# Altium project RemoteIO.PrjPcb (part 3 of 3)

## Sheet RemoteIO_CPU_PWR_RST.SchDoc
size 431 x 279 mm; Date: Not shown in title block; ApprovedBy: Not shown in title block; CheckedBy: Not shown in title block; Author: Not shown in title block; CompanyName: Not shown in title block; Engineer: Not shown in title block; Organization: Not shown in title block; Address1: Not shown in title block; Address2: Not shown in title block; Address3: Not shown in title block; Address4: Not shown in title block; DocumentNumber: 9; Revision: Use project parameter SCH_Rev; SheetNumber: 9; SheetTotal: 14; PageSetup: Record=PageOptions¦CenterHorizontal=True¦CenterVertical=True¦PrintScale=1.00¦XCorrection=1.00¦YCorrection=1.00¦PrintKind=0¦BorderSize=5000000¦LeftOffset=0¦BottomOffset=0¦Orientation=2¦PaperLength=1000¦PaperWidth=1000¦Scale=100¦PaperSource=15¦PrintQuality=600¦MediaType=1¦DitherType=10¦PaperKind=Letter¦PrintScaleMode=1
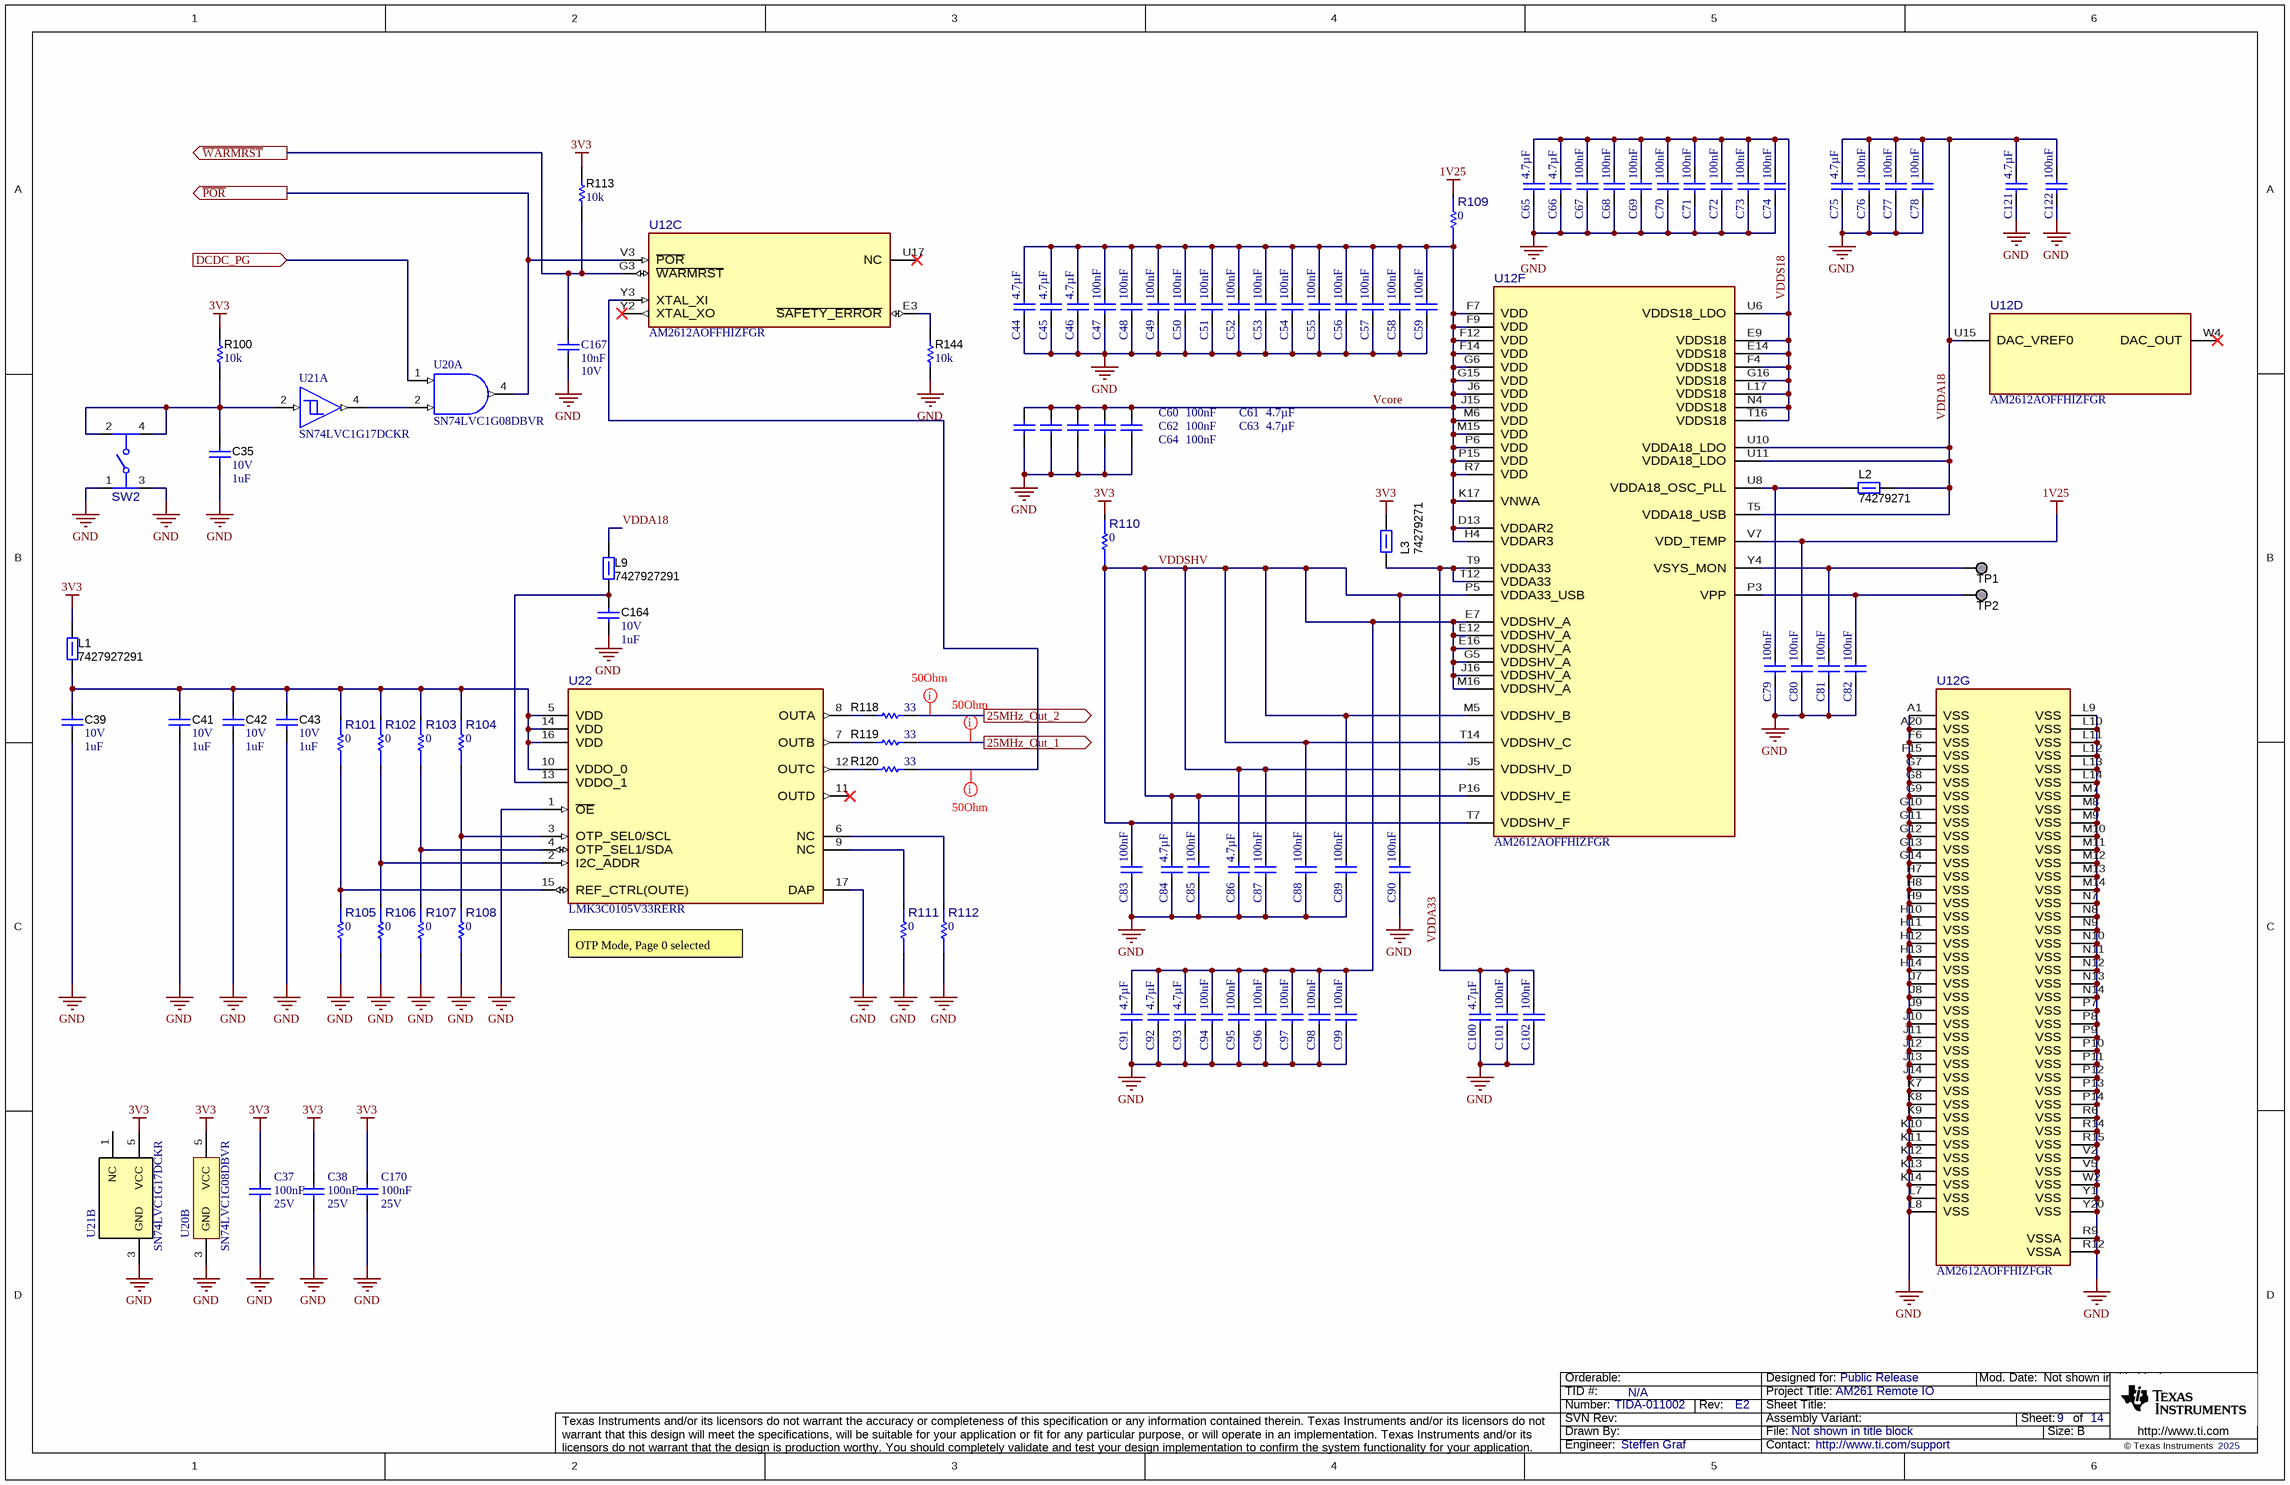
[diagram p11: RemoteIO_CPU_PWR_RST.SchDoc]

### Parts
C35  VDC_V: 10V  ValueDisplayed: 1uF  [0402]  (hidden comment: 885012105012)
C37  Cap_F: 100nF  Rated Voltage (DC): 25V  [WCAP-CSGP_0402_L1W0.5H0.5]  (hidden comment: 885012105018)
C38  Cap_F: 100nF  Rated Voltage (DC): 25V  [WCAP-CSGP_0402_L1W0.5H0.5]  (hidden comment: 885012105018)
C39  VDC_V: 10V  ValueDisplayed: 1uF  [0402]  (hidden comment: 885012105012)
C41  VDC_V: 10V  ValueDisplayed: 1uF  [0402]  (hidden comment: 885012105012)
C42  VDC_V: 10V  ValueDisplayed: 1uF  [0402]  (hidden comment: 885012105012)
C43  VDC_V: 10V  ValueDisplayed: 1uF  [0402]  (hidden comment: 885012105012)
C44  Cap_F: 4.7µF  [WCAP-CSGP_0603_L1.6W0.8H0.8_Reflow]  (hidden comment: 885012106005)
C45  Cap_F: 4.7µF  [WCAP-CSGP_0603_L1.6W0.8H0.8_Reflow]  (hidden comment: 885012106005)
C46  Cap_F: 4.7µF  [WCAP-CSGP_0603_L1.6W0.8H0.8_Reflow]  (hidden comment: 885012106005)
C47  Cap_F: 100nF  [WCAP-CSGP_0201_L0.6W0.3H0.3]  (hidden comment: 885012104009)
C48  Cap_F: 100nF  [WCAP-CSGP_0201_L0.6W0.3H0.3]  (hidden comment: 885012104009)
C49  Cap_F: 100nF  [WCAP-CSGP_0201_L0.6W0.3H0.3]  (hidden comment: 885012104009)
C50  Cap_F: 100nF  [WCAP-CSGP_0201_L0.6W0.3H0.3]  (hidden comment: 885012104009)
C51  Cap_F: 100nF  [WCAP-CSGP_0201_L0.6W0.3H0.3]  (hidden comment: 885012104009)
C52  Cap_F: 100nF  [WCAP-CSGP_0201_L0.6W0.3H0.3]  (hidden comment: 885012104009)
C53  Cap_F: 100nF  [WCAP-CSGP_0201_L0.6W0.3H0.3]  (hidden comment: 885012104009)
C54  Cap_F: 100nF  [WCAP-CSGP_0201_L0.6W0.3H0.3]  (hidden comment: 885012104009)
C55  Cap_F: 100nF  [WCAP-CSGP_0201_L0.6W0.3H0.3]  (hidden comment: 885012104009)
C56  Cap_F: 100nF  [WCAP-CSGP_0201_L0.6W0.3H0.3]  (hidden comment: 885012104009)
C57  Cap_F: 100nF  [WCAP-CSGP_0201_L0.6W0.3H0.3]  (hidden comment: 885012104009)
C58  Cap_F: 100nF  [WCAP-CSGP_0201_L0.6W0.3H0.3]  (hidden comment: 885012104009)
C59  Cap_F: 100nF  [WCAP-CSGP_0201_L0.6W0.3H0.3]  (hidden comment: 885012104009)
C60  Cap_F: 100nF  [WCAP-CSGP_0201_L0.6W0.3H0.3]  (hidden comment: 885012104009)
C61  Cap_F: 4.7µF  [WCAP-CSGP_0603_L1.6W0.8H0.8_Reflow]  (hidden comment: 885012106005)
C62  Cap_F: 100nF  [WCAP-CSGP_0201_L0.6W0.3H0.3]  (hidden comment: 885012104009)
C63  Cap_F: 4.7µF  [WCAP-CSGP_0603_L1.6W0.8H0.8_Reflow]  (hidden comment: 885012106005)
C64  Cap_F: 100nF  [WCAP-CSGP_0201_L0.6W0.3H0.3]  (hidden comment: 885012104009)
C65  Cap_F: 4.7µF  [WCAP-CSGP_0603_L1.6W0.8H0.8_Reflow]  (hidden comment: 885012106005)
C66  Cap_F: 4.7µF  [WCAP-CSGP_0603_L1.6W0.8H0.8_Reflow]  (hidden comment: 885012106005)
C67  Cap_F: 100nF  [WCAP-CSGP_0201_L0.6W0.3H0.3]  (hidden comment: 885012104009)
C68  Cap_F: 100nF  [WCAP-CSGP_0201_L0.6W0.3H0.3]  (hidden comment: 885012104009)
C69  Cap_F: 100nF  [WCAP-CSGP_0201_L0.6W0.3H0.3]  (hidden comment: 885012104009)
C70  Cap_F: 100nF  [WCAP-CSGP_0201_L0.6W0.3H0.3]  (hidden comment: 885012104009)
C71  Cap_F: 100nF  [WCAP-CSGP_0201_L0.6W0.3H0.3]  (hidden comment: 885012104009)
C72  Cap_F: 100nF  [WCAP-CSGP_0201_L0.6W0.3H0.3]  (hidden comment: 885012104009)
C73  Cap_F: 100nF  [WCAP-CSGP_0201_L0.6W0.3H0.3]  (hidden comment: 885012104009)
C74  Cap_F: 100nF  [WCAP-CSGP_0201_L0.6W0.3H0.3]  (hidden comment: 885012104009)
C75  Cap_F: 4.7µF  [WCAP-CSGP_0603_L1.6W0.8H0.8_Reflow]  (hidden comment: 885012106005)
C76  Cap_F: 100nF  [WCAP-CSGP_0201_L0.6W0.3H0.3]  (hidden comment: 885012104009)
C77  Cap_F: 100nF  [WCAP-CSGP_0201_L0.6W0.3H0.3]  (hidden comment: 885012104009)
C78  Cap_F: 100nF  [WCAP-CSGP_0201_L0.6W0.3H0.3]  (hidden comment: 885012104009)
C79  Cap_F: 100nF  [WCAP-CSGP_0201_L0.6W0.3H0.3]  (hidden comment: 885012104009)
C80  Cap_F: 100nF  [WCAP-CSGP_0201_L0.6W0.3H0.3]  (hidden comment: 885012104009)
C81  Cap_F: 100nF  [WCAP-CSGP_0201_L0.6W0.3H0.3]  (hidden comment: 885012104009)
C82  Cap_F: 100nF  [WCAP-CSGP_0201_L0.6W0.3H0.3]  (hidden comment: 885012104009)
C83  Cap_F: 100nF  [WCAP-CSGP_0201_L0.6W0.3H0.3]  (hidden comment: 885012104009)
C84  Cap_F: 4.7µF  [WCAP-CSGP_0603_L1.6W0.8H0.8_Reflow]  (hidden comment: 885012106005)
C85  Cap_F: 100nF  [WCAP-CSGP_0201_L0.6W0.3H0.3]  (hidden comment: 885012104009)
C86  Cap_F: 4.7µF  [WCAP-CSGP_0603_L1.6W0.8H0.8_Reflow]  (hidden comment: 885012106005)
C87  Cap_F: 100nF  [WCAP-CSGP_0201_L0.6W0.3H0.3]  (hidden comment: 885012104009)
C88  Cap_F: 100nF  [WCAP-CSGP_0201_L0.6W0.3H0.3]  (hidden comment: 885012104009)
C89  Cap_F: 100nF  [WCAP-CSGP_0201_L0.6W0.3H0.3]  (hidden comment: 885012104009)
C90  Cap_F: 100nF  [WCAP-CSGP_0201_L0.6W0.3H0.3]  (hidden comment: 885012104009)
C91  Cap_F: 4.7µF  [WCAP-CSGP_0603_L1.6W0.8H0.8_Reflow]  (hidden comment: 885012106005)
C92  Cap_F: 4.7µF  [WCAP-CSGP_0603_L1.6W0.8H0.8_Reflow]  (hidden comment: 885012106005)
C93  Cap_F: 4.7µF  [WCAP-CSGP_0603_L1.6W0.8H0.8_Reflow]  (hidden comment: 885012106005)
C94  Cap_F: 100nF  [WCAP-CSGP_0201_L0.6W0.3H0.3]  (hidden comment: 885012104009)
C95  Cap_F: 100nF  [WCAP-CSGP_0201_L0.6W0.3H0.3]  (hidden comment: 885012104009)
C96  Cap_F: 100nF  [WCAP-CSGP_0201_L0.6W0.3H0.3]  (hidden comment: 885012104009)
C97  Cap_F: 100nF  [WCAP-CSGP_0201_L0.6W0.3H0.3]  (hidden comment: 885012104009)
C98  Cap_F: 100nF  [WCAP-CSGP_0201_L0.6W0.3H0.3]  (hidden comment: 885012104009)
C99  Cap_F: 100nF  [WCAP-CSGP_0201_L0.6W0.3H0.3]  (hidden comment: 885012104009)
C100  Cap_F: 4.7µF  [WCAP-CSGP_0603_L1.6W0.8H0.8_Reflow]  (hidden comment: 885012106005)
C101  Cap_F: 100nF  [WCAP-CSGP_0201_L0.6W0.3H0.3]  (hidden comment: 885012104009)
C102  Cap_F: 100nF  [WCAP-CSGP_0201_L0.6W0.3H0.3]  (hidden comment: 885012104009)
C121  Cap_F: 4.7µF  [WCAP-CSGP_0603_L1.6W0.8H0.8_Reflow]  (hidden comment: 885012106005)
C122  Cap_F: 100nF  [WCAP-CSGP_0201_L0.6W0.3H0.3]  (hidden comment: 885012104009)
C164  VDC_V: 10V  ValueDisplayed: 1uF  [0402]  (hidden comment: 885012105012)
C167  Cap_F: 10nF  Rated Voltage (DC): 10V  [WCAP-CSGP_0402_L1W0.5H0.5]  (hidden comment: 885012205012)
C170  Cap_F: 100nF  Rated Voltage (DC): 25V  [WCAP-CSGP_0402_L1W0.5H0.5]  (hidden comment: 885012105018)
L1  7427927291  [0402]
L2  74279271  [0402]
L3  74279271  [0402]
L9  7427927291  [0402]
R100  ValueDisplayed: 10k  [0402]  (hidden comment: CRCW040210K0JNED)
R101  value 0  [FP-CRCW04020000Z0EDC_0402-MFG]  (hidden comment: CRCW04020000Z0EDC)
R102  value 0  [FP-CRCW04020000Z0EDC_0402-MFG]  (hidden comment: CRCW04020000Z0EDC)
R103  value 0  [FP-CRCW04020000Z0EDC_0402-MFG]  (hidden comment: CRCW04020000Z0EDC)
R104  value 0  [FP-CRCW04020000Z0EDC_0402-MFG]  (hidden comment: CRCW04020000Z0EDC)
R105  value 0  [FP-CRCW04020000Z0EDC_0402-MFG]  (hidden comment: CRCW04020000Z0EDC)
R106  value 0  [FP-CRCW04020000Z0EDC_0402-MFG]  (hidden comment: CRCW04020000Z0EDC)
R107  value 0  [FP-CRCW04020000Z0EDC_0402-MFG]  (hidden comment: CRCW04020000Z0EDC)
R108  value 0  [FP-CRCW04020000Z0EDC_0402-MFG]  (hidden comment: CRCW04020000Z0EDC)
R109  value 0  [FP-CRCW04020000Z0EDC_0402-MFG]  (hidden comment: CRCW04020000Z0EDC)
R110  value 0  [FP-CRCW04020000Z0EDC_0402-MFG]  (hidden comment: CRCW04020000Z0EDC)
R111  value 0  [FP-CRCW04020000Z0EDC_0402-MFG]  (hidden comment: CRCW04020000Z0EDC)
R112  value 0  [FP-CRCW04020000Z0EDC_0402-MFG]  (hidden comment: CRCW04020000Z0EDC)
R113  ValueDisplayed: 10k  [0402]  (hidden comment: CRCW040210K0JNED)
R118  ValueDisplayed: 33  [0402]  (hidden comment: CRCW040233R0JNED)
R119  ValueDisplayed: 33  [0402]  (hidden comment: CRCW040233R0JNED)
R120  ValueDisplayed: 33  [0402]  (hidden comment: CRCW040233R0JNED)
R144  ValueDisplayed: 10k  [0402]  (hidden comment: CRCW040210K0JNED)
SW2  434351045816  [FP-434351045816_SMT_SW_4MM7_4MM5-MFG]  (value not drawn)
TP1  TP_SM_1MM  [TP_SM_1MM]  (value not drawn)  (no BOM)
TP2  TP_SM_1MM  [TP_SM_1MM]  (value not drawn)  (no BOM)
U12  AM2612AOFFHIZFGR  [ZFG0304A-MFG]  (parts C,D,F,G of 7)
U20  SN74LVC1G08DBVR  [DBV0005A_N]  (parts A,B of 2)
U21  SN74LVC1G17DCKR  [DCK0005A_N]  (parts A,B of 2)
U22  LMK3C0105V33RERR  [RER0016A-MFG]

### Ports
25MHz_Out_1 (out), 25MHz_Out_2 (out), DCDC_PG (in), ~{POR} (out), ~{WARMRST} (out)

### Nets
1V25: C80.2 R109.2 U12.V7(VDD_TEMP)
3V3: C37.2 C38.2 C170.2 L1.2 L3.2 R100.2 R110.2 R113.1 U20.5(VCC) U21.5(VCC)
GND: C35.2 C37.1 C38.1 C39.2 C41.2 C42.2 C43.2 C44.1 C45.1 C46.1 C47.1 C48.1 C49.1 C50.1 C51.1 C52.1 C53.1 C54.1 C55.1 C56.1 C57.1 C58.1 C59.1 C60.1 C61.1 C62.1 C63.1 C64.1 C65.1 C66.1 C67.1 C68.1 C69.1 C70.1 C71.1 C72.1 C73.1 C74.1 C75.1 C76.1 C77.1 C78.1 C79.1 C80.1 C81.1 C82.1 C83.1 C84.1 C85.1 C86.1 C87.1 C88.1 C89.1 C90.1 C91.1 C92.1 C93.1 C94.1 C95.1 C96.1 C97.1 C98.1 C99.1 C100.1 C101.1 C102.1 C121.1 C122.1 C164.2 C167.1 C170.1 R105.1 R106.1 R107.1 R108.1 R111.1 R112.1 R144.1 SW2.1 SW2.3 U12.A1(VSS) U12.A20(VSS) U12.F6(VSS) U12.F15(VSS) U12.G7(VSS) U12.G8(VSS) U12.G9(VSS) U12.G10(VSS) U12.G11(VSS) U12.G12(VSS) U12.G13(VSS) U12.G14(VSS) U12.H7(VSS) U12.H8(VSS) U12.H9(VSS) U12.H10(VSS) U12.H11(VSS) U12.H12(VSS) U12.H13(VSS) U12.H14(VSS) U12.J7(VSS) U12.J8(VSS) U12.J9(VSS) U12.J10(VSS) U12.J11(VSS) U12.J12(VSS) U12.J13(VSS) U12.J14(VSS) U12.K7(VSS) U12.K8(VSS) U12.K9(VSS) U12.K10(VSS) U12.K11(VSS) U12.K12(VSS) U12.K13(VSS) U12.K14(VSS) U12.L7(VSS) U12.L8(VSS) U12.L9(VSS) U12.L10(VSS) U12.L11(VSS) U12.L12(VSS) U12.L13(VSS) U12.L14(VSS) U12.M7(VSS) U12.M8(VSS) U12.M9(VSS) U12.M10(VSS) U12.M11(VSS) U12.M12(VSS) U12.M13(VSS) U12.M14(VSS) U12.N7(VSS) U12.N8(VSS) U12.N9(VSS) U12.N10(VSS) U12.N11(VSS) U12.N12(VSS) U12.N13(VSS) U12.N14(VSS) U12.P7(VSS) U12.P8(VSS) U12.P9(VSS) U12.P10(VSS) U12.P11(VSS) U12.P12(VSS) U12.P13(VSS) U12.P14(VSS) U12.R6(VSS) U12.R9(VSSA) U12.R12(VSSA) U12.R14(VSS) U12.R15(VSS) U12.V2(VSS) U12.V5(VSS) U12.W2(VSS) U12.Y1(VSS) U12.Y20(VSS) U20.3(GND) U21.3(GND) U22.1(~{OE}) U22.17(DAP)
25MHz: R119.2 ; port 25MHz_Out_1
25MHz: R118.2 ; port 25MHz_Out_2  [a separate net that carries the same name]
~{POR}: U12.V3(~{POR}) U20.4(Y) ; port ~{POR}
~{WARMRST}: C167.2 R113.2 U12.G3(~{WARMRST}) ; port ~{WARMRST}
DCDC_PG: U20.1(A) ; port DCDC_PG
Vcore: C44.2 C45.2 C46.2 C47.2 C48.2 C49.2 C50.2 C51.2 C52.2 C53.2 C54.2 C55.2 C56.2 C57.2 C58.2 C59.2 C60.2 C61.2 C62.2 C63.2 C64.2 R109.1 U12.D13(VDDAR2) U12.F7(VDD) U12.F9(VDD) U12.F12(VDD) U12.F14(VDD) U12.G6(VDD) U12.G15(VDD) U12.H4(VDDAR3) U12.J6(VDD) U12.J15(VDD) U12.K17(VNWA) U12.M6(VDD) U12.M15(VDD) U12.P6(VDD) U12.P15(VDD) U12.R7(VDD)
VDDA18: C75.2 C76.2 C77.2 C78.2 C121.2 C122.2 L2.2 L9.2 U12.T5(VDDA18_USB) U12.U10(VDDA18_LDO) U12.U11(VDDA18_LDO) U12.U15(DAC_VREF0)
VDDA33: C100.2 C101.2 C102.2 L3.1 U12.T9(VDDA33) U12.T12(VDDA33)
VDDS18: C65.2 C66.2 C67.2 C68.2 C69.2 C70.2 C71.2 C72.2 C73.2 C74.2 U12.E9(VDDS18) U12.E14(VDDS18) U12.F4(VDDS18) U12.G16(VDDS18) U12.L17(VDDS18) U12.N4(VDDS18) U12.T16(VDDS18) U12.U6(VDDS18_LDO)
VDDSHV: C83.2 C84.2 C85.2 C86.2 C87.2 C88.2 C89.2 C90.2 C91.2 C92.2 C93.2 C94.2 C95.2 C96.2 C97.2 C98.2 C99.2 R110.1 U12.E7(VDDSHV_A) U12.E12(VDDSHV_A) U12.E16(VDDSHV_A) U12.G5(VDDSHV_A) U12.J5(VDDSHV_D) U12.J16(VDDSHV_A) U12.M5(VDDSHV_B) U12.M16(VDDSHV_A) U12.P5(VDDA33_USB) U12.P16(VDDSHV_E) U12.T7(VDDSHV_F) U12.T14(VDDSHV_C)
NetC35_1: C35.1 R100.1 SW2.2 SW2.4 U21.2(A)
NetC39_1: C39.1 C41.1 C42.1 C43.1 L1.1 R101.2 R102.2 R103.2 R104.2 U22.5(VDD) U22.10(VDDO_0) U22.14(VDD) U22.16(VDD)
NetC79_2: C79.2 L2.1 U12.U8(VDDA18_OSC_PLL)
NetC81_2: C81.2 TP1.1 U12.Y4(VSYS_MON)
NetC82_2: C82.2 TP2.1 U12.P3(VPP)
NetC164_1: C164.1 L9.1 U22.13(VDDO_1)
NetR101_1: R101.1 R105.2 U22.15(REF_CTRL(OUTE))
NetR102_1: R102.1 R106.2 U22.2(I2C_ADDR)
NetR103_1: R103.1 R107.2 U22.4(OTP_SEL1/SDA)
NetR104_1: R104.1 R108.2 U22.3(OTP_SEL0/SCL)
NetR111_2: R111.2 U22.9(NC)
NetR112_2: R112.2 U22.6(NC)
NetR118_1: R118.1 U22.8(OUTA)
NetR119_1: R119.1 U22.7(OUTB)
NetR120_1: R120.1 U22.12(OUTC)
NetR120_2: R120.2 U12.Y3(XTAL_XI)
NetR144_2: R144.2 U12.E3(~{SAFETY_ERROR})
NetU20_2: U20.2(B) U21.4(Y)

Not connected (* = marked no-connect by the designer): U12 U17(NC)* W4(DAC_OUT)* Y2(XTAL_XO)*; U21 1(NC); U22 11(OUTD)*

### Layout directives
net class S50: 25MHz, NetR120_2

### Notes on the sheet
- (near U22) OTP Mode, Page 0 selected

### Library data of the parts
C35 C39 C41-C43 C164 = CMP-0064924-2: CAP, CERM, 1 uF, 10 V,+/- 20%, X5R, 0402; Manufacturer: Wurth Elektronik; TaMin_C: -55°C; Polarized: N; SizeAreaWB_mm2: 3; Value1: Unknown; U/M: EA; Value: 1uF; TaMax_C: 85°C; SizeZ_mm: 0.6; SizeX_mm: 1; SizeY_mm: 0.5; Cap_F: 1µF; AEC Category: Q200
C37 C38 C170 = CMP-0119143-1: WCAP-CSGP Multilayer Ceramic Chip Capacitor, General Purpose, size 0402, X5R, 100nF, 25VDC; Manufacturer: Wurth Elektronik; PartNumber: '885012105018; Capacitance Tolerance: +/-20%; Case/Size Code: 0402; Dissipation Factor: 10%; Insulation Resistance: 5GOhm; Technical Reference: X5R0402104M025DFCT10000
C44-C46 C61 C63 C65 C66 C75 C84 C86 C91-C93 C100 C121 = CMP-0119149-1: WCAP-CSGP Multilayer Ceramic Chip Capacitor, General Purpose, size 0603, X5R, 4.7µF, 6.3VDC; Manufacturer: Wurth Elektronik; Capacitance Tolerance: +/-20%; Case/Size Code: 0603; Dissipation Factor: 10%; Insulation Resistance: 0.02GOhm; Rated Voltage (DC): 6.3V; Technical Reference: X5R0603475M6R3DFCT10000
C47-C60 C62 C64 C67-C74 C76-C83 C85 C87-C90 C94-C99 C101 C102 C122 = CMP-0119120-1: WCAP-CSGP Multilayer Ceramic Chip Capacitor, General Purpose, size 0201, X5R Class II, 100nF, 6.3VDC; Manufacturer: Wurth Elektronik; Capacitance Tolerance: +/-10%; Case/Size Code: 0201; Dissipation Factor: 10%; Insulation Resistance: 0.5GOhm; Rated Voltage (DC): 6.3V; Technical Reference: X5R0201104K6R3DFCT10000
C167 = CMP-0119242-1: WCAP-CSGP Multilayer Ceramic Chip Capacitor, General Purpose, size 0402, X7R, 10nF, 10VDC; Manufacturer: Wurth Elektronik; Capacitance Tolerance: +/-10%; Case/Size Code: 0402; Dissipation Factor: 5%; Insulation Resistance: 10GOhm; Technical Reference: X7R0402103K010DFCT10000
L1 L9 = CMP-0003233-1: Ferrite Bead, 600 ohm @ 100 MHz, 0.3 A, 0402; Manufacturer: Wurth Elektronik; Ztyp@1GHz_Ohm: 385.838; ZTyp@100MHz_Ohm: 600; SizeAreaWB_mm2: 3; DCR_ohm: 0.6; Value1: 0.6 ohm; Value: 600 ohm; Imax_A: 300mA; SizeX_mm: 1; SizeY_mm: 0.5; Value2: 0.3A
L2 L3 = CMP-0003214-1: Ferrite Bead, 120 ohm @ 100 MHz, 0.5 A, 0402; Manufacturer: Wurth Elektronik; Ztyp@1GHz_Ohm: 175.42; ZTyp@100MHz_Ohm: 120; SizeAreaWB_mm2: 3; DCR_ohm: 0.2; Value1: 0.2 ohm; Value: 120 ohm; Imax_A: 500mA; SizeZ_mm: 0.6; SizeX_mm: 1; SizeY_mm: 0.5; Value2: 0.5A
R100 R113 R144 = CMP-0026825-5: RES, 10 k, 5%, 0.063 W, AEC-Q200 Grade 0, 0402; Manufacturer: Vishay-Dale; Power_W: 63mW; TempCo: 200 ppm/C; Value_Code: 10k0; Value: 10k; EIA_Code: E24; SizeX_mm: 1; SizeY_mm: 0.5; SizeZ_mm: 0.6; Value2: 0.063W; AEC Qualified: Y; VDC_V: 50V; AEC Category: Q200; AEC Grade: 0
R101-R112 = CMP-0093210-1: Jumper 0.063W, 1/16W Chip Resistor 0402 (1005 Metric) - Thick Film; Manufacturer: Vishay; AEC Qualified: No; VDC_V: 50V; Power_W: 63mW; SizeZ_mm: 0.35mm
R118-R120 = CMP-0026908-3: RES, 33, 5%, 0.063 W, AEC-Q200 Grade 0, 0402; Manufacturer: Vishay-Dale; Power_W: 63mW; TempCo: 200 ppm/C; Value_Code: 33R0; Value: 33; EIA_Code: E24; SizeX_mm: 1; SizeY_mm: 0.5; SizeZ_mm: 0.6; Value2: 0.063W; AEC Qualified: Y; VDC_V: 50V; AEC Category: Q200; AEC Grade: 0
SW2 = CMP-0093456-1: Tactile Switch SPST-NO Side Actuated Surface Mount, Right Angle; Manufacturer: Wurth Electronics; Operating Force: 160gf; SizeZ_mm: 1.75mm; AEC Qualified: No; Electromechanical Life: 200000Cycles; VDC_V: 12V; Contact Current Rating: 50mA; Coil Resistance_ohm: 100mΩ
TP1 TP2 = CMP-0003825-1: 1mm Test Point, SMT; Manufacturer: Any
U12 = CMP-0126016-1: ARM® Cortex®-R5F Sitara™ Microcontroller IC 32-Bit Dual-Core 500MHz 512KB (512K x 8) Tightly Coupled Memory (TCM) 304-NFBGA (13.25x13.25); Manufacturer: Texas Instruments; SizeZ_mm: 1.3mm; AEC Qualified: No; Core Architecture: ARM Cortex-R5F; Data Bus Width: 32bits; Interface: I2C,SPI,UART,CAN,USB,LIN,Ethernet; Max Supply Voltage: 3.465V; Min Supply Voltage: 1.14V; Number Of A/D Converters: 3; Number Of Adc Channels: 7; Number Of Cores: 2; Number Of Ethernet Channels: 1; Number Of I/Os: 141; Number Of Pwm Channels: 10; Number Of Spi Channels: 4; Number Of Uart Channels: 6; Ram Size: 1.5MBytes; Standoff Height: 0.23mm; TJmax_C: +125°C
U20 = CMP-0051588-2: Single 2-Input Positive-AND Gate, DBV0005A, LARGE T&R; Manufacturer: Texas Instruments; Logic: True; ICC @ Nom Voltage(Max)(mA): 0.01; VCC(Min)(V): 1.65; Bits(#): 1; Rating: Catalog; Schmitt Trigger: No; Voltage(Nom)(V): 1.8,2.5,3.3,5; Output Drive (IOL/IOH)(Max)(mA): 32/-32; Gate Type: AND; tpd @ Nom Voltage(Max)(ns): 4.5,6,4,5; VCC(Max)(V): 5.5; Output Type: CMOS; F @ Nom Voltage(Max)(Mhz): 150; Input Type: CMOS/TTL; Technology Family: LVC; AEC Category: Q200; AEC Qualified: N; CompType: IC
U21 = CMP-0051704-3: Single Schmitt-Trigger Buffer, DCK0005A, LARGE T&R; Manufacturer: Texas Instruments; tpd @ Nom Voltage(Max)(ns): 11,6.5,5.5,5; Bits(#): 1; VCC(Min)(V): 1.65; F @ Nom Voltage(Max)(Mhz): 150; VCC(Max)(V): 5.5; Input Type: CMOS/TTL; Sub-Family: Non-Inverting Buffer/Driver; Output Type: CMOS; Output Drive (IOL/IOH)(Max)(mA): 32/-32; 3-State Output: No; Logic: True; ICC @ Nom Voltage(Max)(mA): 0.01; Voltage(Nom)(V): 1.8,2.5,3.3,5; Rating: Catalog; Schmitt Trigger: Yes; Technology Family: LVC; AEC Category: Q200; AEC Qualified: N; CompType: IC; SizeAreaWB_mm2: 9.3; SizeArea_mm2: 4.2; SizeX_mm: 2.1; SizeY_mm: 2.0; SizeZ_mm: 1.1
U22 = CMP-0126121-1: 5 output reference-less clock generator with bulk acoustic wave (BAW) 16-TQFN -40 to 85; Manufacturer: Texas Instruments; SizeZ_mm: 1.2mm; AEC Qualified: No; Interface: I2C; Max Frequency: 200MHz; Max Supply Voltage: 3.465V; Min Supply Voltage: 1.71V; Number Of Outputs: 5; Standoff Height: 0mm; TaMax_C: +85°C; TaMin_C: -40°C; TJmax_C: +105°C

## Sheet RemoteIO_CPU_MISC.SchDoc
size 431 x 279 mm; Date: Not shown in title block; ApprovedBy: Not shown in title block; CheckedBy: Not shown in title block; Author: Not shown in title block; CompanyName: Not shown in title block; Engineer: Not shown in title block; Organization: Not shown in title block; Address1: Not shown in title block; Address2: Not shown in title block; Address3: Not shown in title block; Address4: Not shown in title block; DocumentNumber: 10; Revision: Use project parameter SCH_Rev; SheetNumber: 10; SheetTotal: 14; PageSetup: Record=PageOptions¦CenterHorizontal=True¦CenterVertical=True¦PrintScale=1.00¦XCorrection=1.00¦YCorrection=1.00¦PrintKind=0¦BorderSize=5000000¦LeftOffset=0¦BottomOffset=0¦Orientation=2¦PaperLength=1000¦PaperWidth=1000¦Scale=100¦PaperSource=15¦PrintQuality=600¦MediaType=1¦DitherType=10¦PaperKind=Letter¦PrintScaleMode=1
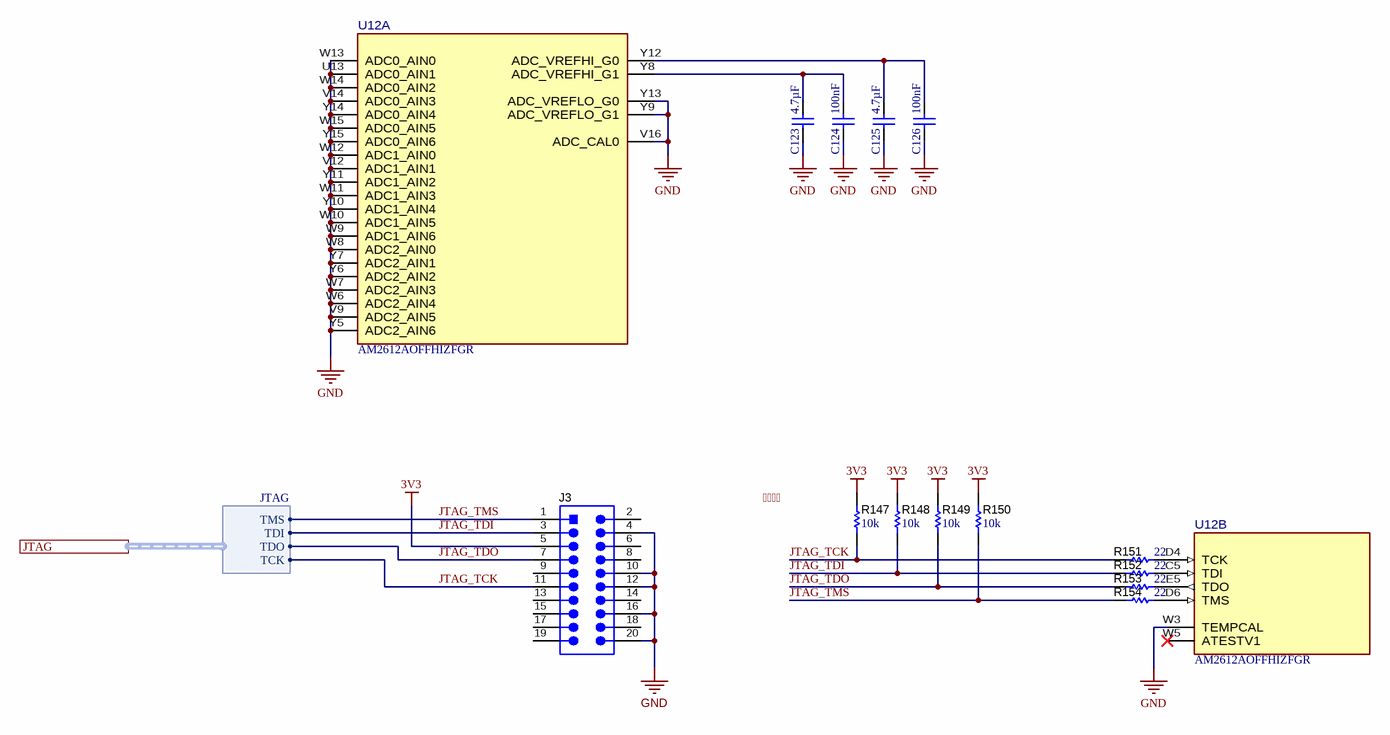
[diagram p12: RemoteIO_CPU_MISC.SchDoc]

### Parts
C123  Cap_F: 4.7µF  [WCAP-CSGP_0603_L1.6W0.8H0.8_Reflow]  (hidden comment: 885012106005)
C124  Cap_F: 100nF  [WCAP-CSGP_0201_L0.6W0.3H0.3]  (hidden comment: 885012104009)
C125  Cap_F: 4.7µF  [WCAP-CSGP_0603_L1.6W0.8H0.8_Reflow]  (hidden comment: 885012106005)
C126  Cap_F: 100nF  [WCAP-CSGP_0201_L0.6W0.3H0.3]  (hidden comment: 885012104009)
J3  FTR-110-51-S-D-06  [Samtec_FTR-110-51-x-D-06]  (value not drawn)
R147  ValueDisplayed: 10k  [0402]  (hidden comment: CRCW040210K0JNED)
R148  ValueDisplayed: 10k  [0402]  (hidden comment: CRCW040210K0JNED)
R149  ValueDisplayed: 10k  [0402]  (hidden comment: CRCW040210K0JNED)
R150  ValueDisplayed: 10k  [0402]  (hidden comment: CRCW040210K0JNED)
R151  ValueDisplayed: 22  [0402]  (hidden comment: CRCW040222R0JNED)
R152  ValueDisplayed: 22  [0402]  (hidden comment: CRCW040222R0JNED)
R153  ValueDisplayed: 22  [0402]  (hidden comment: CRCW040222R0JNED)
R154  ValueDisplayed: 22  [0402]  (hidden comment: CRCW040222R0JNED)
U12  AM2612AOFFHIZFGR  [ZFG0304A-MFG]  (parts A,B of 7)

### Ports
JTAG (harness JTAG)

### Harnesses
JTAG: TMS, TDI, TDO, TCK

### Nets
3V3: J3.5 R147.2 R148.2 R149.2 R150.2
GND: C123.1 C124.1 C125.1 C126.1 J3.4 J3.10 J3.12 J3.16 J3.20 U12.U13(ADC0_AIN1) U12.V9(ADC2_AIN5) U12.V12(ADC1_AIN1) U12.V14(ADC0_AIN3) U12.V16(ADC_CAL0) U12.W3(TEMPCAL) U12.W6(ADC2_AIN4) U12.W7(ADC2_AIN3) U12.W8(ADC2_AIN0) U12.W9(ADC1_AIN6) U12.W10(ADC1_AIN5) U12.W11(ADC1_AIN3) U12.W12(ADC1_AIN0) U12.W13(ADC0_AIN0) U12.W14(ADC0_AIN2) U12.W15(ADC0_AIN5) U12.Y5(ADC2_AIN6) U12.Y6(ADC2_AIN2) U12.Y7(ADC2_AIN1) U12.Y9(ADC_VREFLO_G1) U12.Y10(ADC1_AIN4) U12.Y11(ADC1_AIN2) U12.Y13(ADC_VREFLO_G0) U12.Y14(ADC0_AIN4) U12.Y15(ADC0_AIN6)
JTAG_TCK: J3.11 R147.1 R151.1 ; port JTAG.TCK
JTAG_TDI: J3.3 R148.1 R152.1 ; port JTAG.TDI
JTAG_TDO: J3.7 R149.1 R153.1 ; port JTAG.TDO
JTAG_TMS: J3.1 R150.1 R154.1 ; port JTAG.TMS
NetC123_2: C123.2 C124.2 U12.Y8(ADC_VREFHI_G1)
NetC125_2: C125.2 C126.2 U12.Y12(ADC_VREFHI_G0)
NetR151_2: R151.2 U12.D4(TCK)
NetR152_2: R152.2 U12.C5(TDI)
NetR153_2: R153.2 U12.E5(TDO)
NetR154_2: R154.2 U12.D6(TMS)

Not connected (* = marked no-connect by the designer): J3 2 6 8 9 13 14 15 17 18 19; U12 W5(ATESTV1)*

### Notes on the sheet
- Labels drawn without touching a wire or pin: 

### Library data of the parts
C123 C125 = CMP-0119149-1: as C44 on sheet RemoteIO_CPU_PWR_RST
C124 C126 = CMP-0119120-1: as C47 on sheet RemoteIO_CPU_PWR_RST
J3 = CMP-0075640-2: Header, 1.27mm, 10x2, Tin, SMT; Manufacturer: Samtec; Pitch_mm: 1.27; Gender: Male; Cert_UL: Y; Green_REACh: Passed; Current_A: 3.1A; Shrouded: N; RowSpacing_mm: 2.54; Green_Lifecycle: Active; Row_Count: 2
R147-R150 = CMP-0026825-5: as R100 on sheet RemoteIO_CPU_PWR_RST
R151-R154 = CMP-0026880-3: RES, 22, 5%, 0.063 W, AEC-Q200 Grade 0, 0402; Manufacturer: Vishay-Dale; Power_W: 63mW; TempCo: 200 ppm/C; Value_Code: 22R0; Value: 22; EIA_Code: E24; SizeX_mm: 1; SizeY_mm: 0.5; SizeZ_mm: 0.6; Value2: 0.063W; AEC Qualified: Y; VDC_V: 50V; AEC Category: Q200; AEC Grade: 0
U12 = CMP-0126016-1: as U12 on sheet RemoteIO_CPU_PWR_RST

## Sheet RemoteIO_XDS110.SchDoc
size 431 x 279 mm; Date: Not shown in title block; ApprovedBy: Not shown in title block; CheckedBy: Not shown in title block; Author: Not shown in title block; CompanyName: Not shown in title block; Engineer: Not shown in title block; Organization: Not shown in title block; Address1: Not shown in title block; Address2: Not shown in title block; Address3: Not shown in title block; Address4: Not shown in title block; DocumentNumber: 13; Revision: Use project parameter SCH_Rev; SheetNumber: 13; SheetTotal: 14; PageSetup: Record=PageOptions¦CenterHorizontal=True¦CenterVertical=True¦PrintScale=1.00¦XCorrection=1.00¦YCorrection=1.00¦PrintKind=0¦BorderSize=5000000¦LeftOffset=0¦BottomOffset=0¦Orientation=2¦PaperLength=1000¦PaperWidth=1000¦Scale=100¦PaperSource=15¦PrintQuality=600¦MediaType=1¦DitherType=10¦PaperKind=Letter¦PrintScaleMode=1
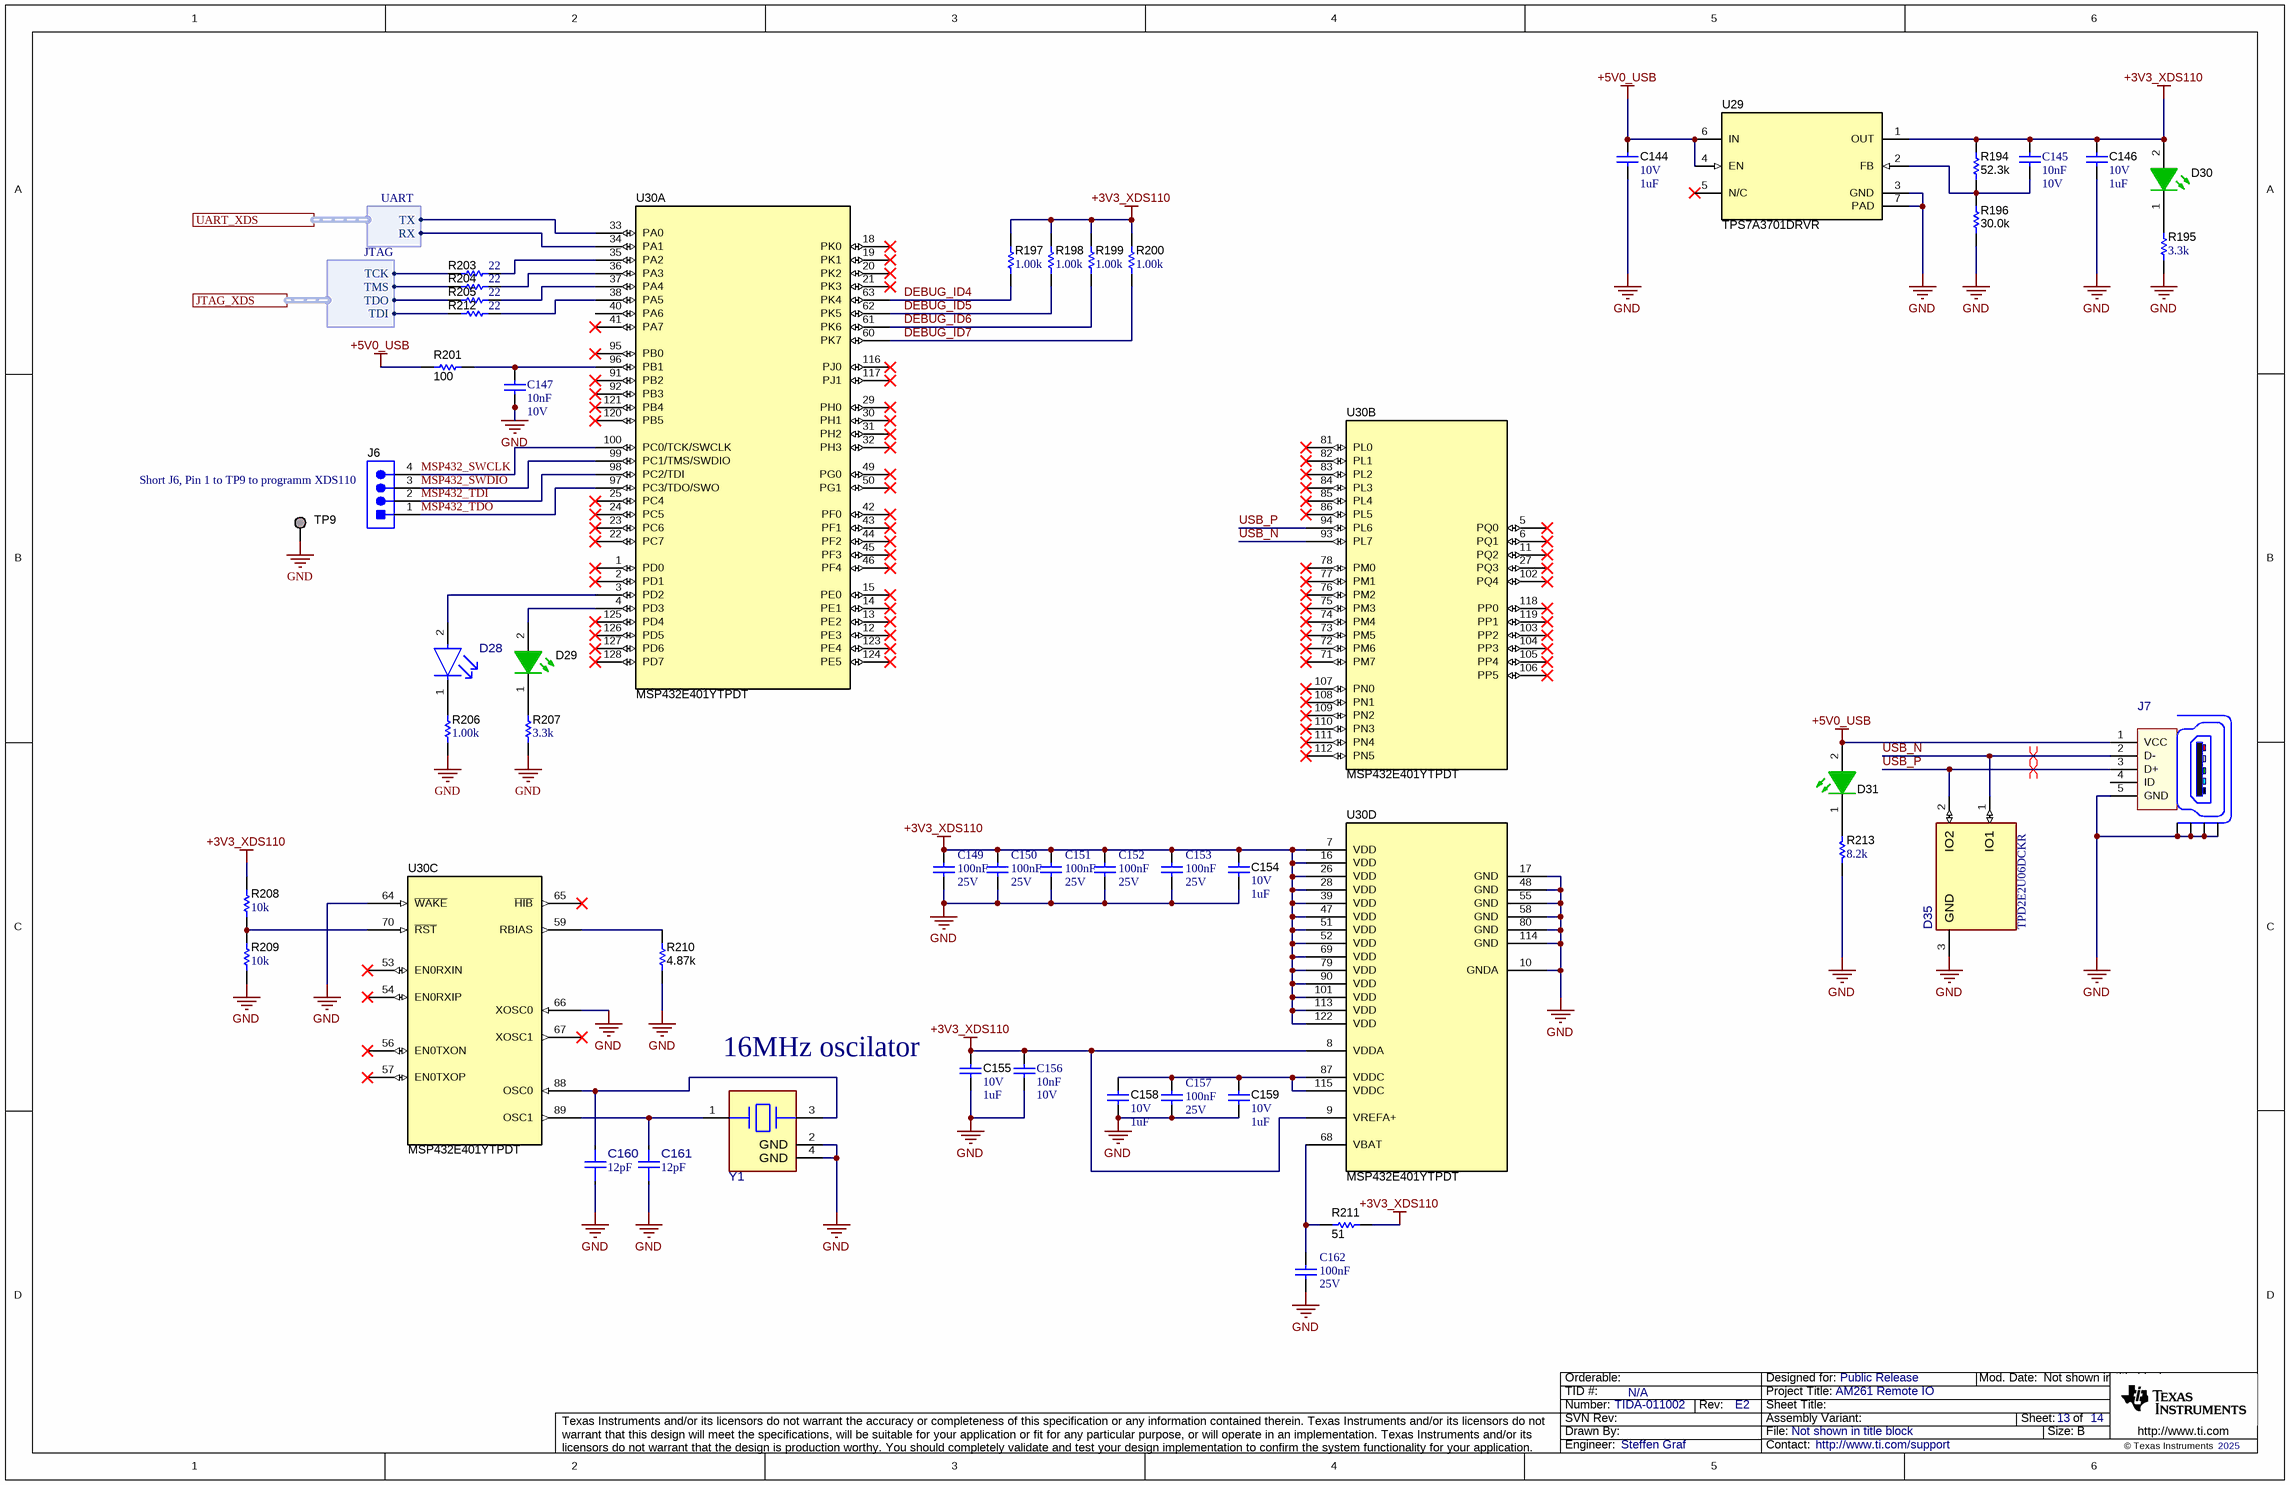
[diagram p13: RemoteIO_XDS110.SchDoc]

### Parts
C144  VDC_V: 10V  ValueDisplayed: 1uF  [0402]  (hidden comment: 885012105012)
C145  Cap_F: 10nF  Rated Voltage (DC): 10V  [WCAP-CSGP_0402_L1W0.5H0.5]  (hidden comment: 885012205012)
C146  VDC_V: 10V  ValueDisplayed: 1uF  [0402]  (hidden comment: 885012105012)
C147  Cap_F: 10nF  Rated Voltage (DC): 10V  [WCAP-CSGP_0402_L1W0.5H0.5]  (hidden comment: 885012205012)
C149  Cap_F: 100nF  Rated Voltage (DC): 25V  [WCAP-CSGP_0402_L1W0.5H0.5]  (hidden comment: 885012105018)
C150  Cap_F: 100nF  Rated Voltage (DC): 25V  [WCAP-CSGP_0402_L1W0.5H0.5]  (hidden comment: 885012105018)
C151  Cap_F: 100nF  Rated Voltage (DC): 25V  [WCAP-CSGP_0402_L1W0.5H0.5]  (hidden comment: 885012105018)
C152  Cap_F: 100nF  Rated Voltage (DC): 25V  [WCAP-CSGP_0402_L1W0.5H0.5]  (hidden comment: 885012105018)
C153  Cap_F: 100nF  Rated Voltage (DC): 25V  [WCAP-CSGP_0402_L1W0.5H0.5]  (hidden comment: 885012105018)
C154  VDC_V: 10V  ValueDisplayed: 1uF  [0402]  (hidden comment: 885012105012)
C155  VDC_V: 10V  ValueDisplayed: 1uF  [0402]  (hidden comment: 885012105012)
C156  Cap_F: 10nF  Rated Voltage (DC): 10V  [WCAP-CSGP_0402_L1W0.5H0.5]  (hidden comment: 885012205012)
C157  Cap_F: 100nF  Rated Voltage (DC): 25V  [WCAP-CSGP_0402_L1W0.5H0.5]  (hidden comment: 885012105018)
C158  VDC_V: 10V  ValueDisplayed: 1uF  [0402]  (hidden comment: 885012105012)
C159  VDC_V: 10V  ValueDisplayed: 1uF  [0402]  (hidden comment: 885012105012)
C160  ValueDisplayed: 12pF  [FP-885392005127_0402-MFG]  (hidden comment: 885392005127)
C161  ValueDisplayed: 12pF  [FP-885392005127_0402-MFG]  (hidden comment: 885392005127)
C162  Cap_F: 100nF  Rated Voltage (DC): 25V  [WCAP-CSGP_0402_L1W0.5H0.5]  (hidden comment: 885012105018)
D28  150040RS73240  [FP-150040RS73220_0402-MFG]  (value not drawn)
D29  150040GS73240  [WL-SMCC_0402_Green]  (value not drawn)
D30  150040GS73240  [WL-SMCC_0402_Green]  (value not drawn)
D31  150040GS73240  [WL-SMCC_0402_Green]  (value not drawn)
D35  TPD2E2U06DCKR  [DCK0003A-MFG]
J6  SPI Debug Header  [WURTH_61300411121]  (value not drawn)
J7  629105150521  [FP-629105150521_CONN_USB_8MM0_6MM6-MFG]  (value not drawn)
R194  ValueDisplayed: 52.3k  [0402]  (hidden comment: CRCW040252K3FKED)
R195  ValueDisplayed: 3.3k  [0402]  (hidden comment: CRCW04023K30JNED)
R196  ValueDisplayed: 30.0k  [0402]  (hidden comment: CRCW040230K0FKED)
R197  ValueDisplayed: 1.00k  [0402]  (hidden comment: CRCW04021K00FKED)
R198  ValueDisplayed: 1.00k  [0402]  (hidden comment: CRCW04021K00FKED)
R199  ValueDisplayed: 1.00k  [0402]  (hidden comment: CRCW04021K00FKED)
R200  ValueDisplayed: 1.00k  [0402]  (hidden comment: CRCW04021K00FKED)
R201  ValueDisplayed: 100  [0402]  (hidden comment: CRCW0402100RJNED)
R203  ValueDisplayed: 22  [0402]  (hidden comment: CRCW040222R0JNED)
R204  ValueDisplayed: 22  [0402]  (hidden comment: CRCW040222R0JNED)
R205  ValueDisplayed: 22  [0402]  (hidden comment: CRCW040222R0JNED)
R206  ValueDisplayed: 1.00k  [0402]  (hidden comment: CRCW04021K00FKED)
R207  ValueDisplayed: 3.3k  [0402]  (hidden comment: CRCW04023K30JNED)
R208  ValueDisplayed: 10k  [0402]  (hidden comment: CRCW040210K0JNED)
R209  ValueDisplayed: 10k  [0402]  (hidden comment: CRCW040210K0JNED)
R210  ValueDisplayed: 4.87k  [0402]  (hidden comment: CRCW04024K87FKED)
R211  ValueDisplayed: 51  [0402]  (hidden comment: CRCW040251R0JNED)
R212  ValueDisplayed: 22  [0402]  (hidden comment: CRCW040222R0JNED)
R213  ValueDisplayed: 8.2k  [0603]  (hidden comment: CRCW06038K20JNEA)
TP9  TESTPOINT  [TP_50MIL-25MILHOLE]  (value not drawn)  (no BOM)
U29  TPS7A3701DRVR  [DRV0006A]
U30  MSP432E401YTPDT  [PDT0128A]  (parts A,B,C,D of 4)
Y1  830064296  [FP-830064296_SMT4_3MM4_2MM7-MFG]  (value not drawn)

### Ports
JTAG_XDS (harness JTAG), UART_XDS (harness UART)

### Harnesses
UART: TX, RX
JTAG: TMS, TDI, TDO, TCK

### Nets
+3V3_XDS110: C145.2 C146.1 C149.2 C150.2 C151.2 C152.2 C153.2 C154.1 C155.1 C156.2 D30.2(A) R194.2 R197.2 R198.2 R199.2 R200.2 R208.1 R211.2 U29.1(OUT) U30.7(VDD) U30.8(VDDA) U30.9(VREFA+) U30.16(VDD) U30.26(VDD) U30.28(VDD) U30.39(VDD) U30.47(VDD) U30.51(VDD) U30.52(VDD) U30.69(VDD) U30.79(VDD) U30.90(VDD) U30.101(VDD) U30.113(VDD) U30.122(VDD)
+5V0_USB: C144.1 D31.2(A) J7.1(VCC) R201.1 U29.4(EN) U29.6(IN)
GND: C144.2 C146.2 C147.1 C149.1 C150.1 C151.1 C152.1 C153.1 C154.2 C155.2 C156.1 C157.1 C158.2 C159.2 C160.1 C161.1 C162.1 D35.3(GND) J7.5(GND) J7.Z1(Shield) J7.Z2(Shield) J7.Z3(Shield) J7.Z4(Shield) R195.1 R196.1 R206.1 R207.1 R209.2 R210.1 R213.1 TP9.1 U29.3(GND) U29.7(PAD) U30.10(GNDA) U30.17(GND) U30.48(GND) U30.55(GND) U30.58(GND) U30.64(~{WAKE}) U30.66(XOSC0) U30.80(GND) U30.114(GND) Y1.2(GND) Y1.4(GND)
DEBUG_ID4: R197.1 U30.63(PK4)
DEBUG_ID5: R198.1 U30.62(PK5)
DEBUG_ID6: R199.1 U30.61(PK6)
DEBUG_ID7: R200.1 U30.60(PK7)
JTAG_TCK: R203.1 ; port JTAG_XDS.TCK
JTAG_TDI: R212.1 ; port JTAG_XDS.TDI
JTAG_TDO: R205.1 ; port JTAG_XDS.TDO
JTAG_TMS: R204.1 ; port JTAG_XDS.TMS
MSP432_SWCLK: J6.4 U30.100(PC0/TCK/SWCLK)
MSP432_SWDIO: J6.3 U30.99(PC1/TMS/SWDIO)
MSP432_TDI: J6.2 U30.98(PC2/TDI)
MSP432_TDO: J6.1 U30.97(PC3/TDO/SWO)
UART0_RX: U30.34(PA1) ; port UART_XDS.RX
UART0_TX: U30.33(PA0) ; port UART_XDS.TX
USB_N: D35.1(IO1) J7.2(D-) U30.93(PL7)
USB_P: D35.2(IO2) J7.3(D+) U30.94(PL6)
NetC145_1: C145.1 R194.1 R196.2 U29.2(FB)
NetC147_2: C147.2 R201.2 U30.96(PB1)
NetC157_2: C157.2 C158.1 C159.1 U30.87(VDDC) U30.115(VDDC)
NetC160_2: C160.2 U30.88(OSC0) Y1.3(2_Crystal)
NetC161_2: C161.2 U30.89(OSC1) Y1.1(1_Crystal)
NetC162_2: C162.2 R211.1 U30.68(VBAT)
NetD28_1: D28.1(CATHODE) R206.2
NetD28_2: D28.2(ANODE) U30.3(PD2)
NetD29_1: D29.1(K) R207.2
NetD29_2: D29.2(A) U30.4(PD3)
NetD30_1: D30.1(K) R195.2
NetD31_1: D31.1(K) R213.2
NetR203_2: R203.2 U30.35(PA2)
NetR204_2: R204.2 U30.36(PA3)
NetR205_2: R205.2 U30.37(PA4)
NetR208_2: R208.2 R209.1 U30.70(~{RST})
NetR210_2: R210.2 U30.59(RBIAS)
NetR212_2: R212.2 U30.38(PA5)

Not connected (* = marked no-connect by the designer): J7 4(ID); U29 5(N/C)*; U30 1(PD0)* 2(PD1)* 5(PQ0)* 6(PQ1)* 11(PQ2)* 12(PE3)* 13(PE2)* 14(PE1)* 15(PE0)* 18(PK0)* 19(PK1)* 20(PK2)* 21(PK3)* 22(PC7)* 23(PC6)* 24(PC5)* 25(PC4)* 27(PQ3)* 29(PH0)* 30(PH1)* 31(PH2)* 32(PH3)* 40(PA6) 41(PA7)* 42(PF0)* 43(PF1)* 44(PF2)* 45(PF3)* 46(PF4)* 49(PG0)* 50(PG1)* 53(EN0RXIN)* 54(EN0RXIP)* 56(EN0TXON)* 57(EN0TXOP)* 65(~{HIB})* 67(XOSC1)* 71(PM7)* 72(PM6)* 73(PM5)* 74(PM4)* 75(PM3)* 76(PM2)* 77(PM1)* 78(PM0)* 81(PL0)* 82(PL1)* 83(PL2)* 84(PL3)* 85(PL4)* 86(PL5)* 91(PB2)* 92(PB3)* 95(PB0)* 102(PQ4)* 103(PP2)* 104(PP3)* 105(PP4)* 106(PP5)* 107(PN0)* 108(PN1)* 109(PN2)* 110(PN3)* 111(PN4)* 112(PN5)* 116(PJ0)* 117(PJ1)* 118(PP0)* 119(PP1)* 120(PB5)* 121(PB4)* 123(PE4)* 124(PE5)* 125(PD4)* 126(PD5)* 127(PD6)* 128(PD7)*

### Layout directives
differential pair; differential pair class D90: USB_N, USB_P

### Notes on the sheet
- (near J6) Short J6, Pin 1 to TP9 to programm XDS110
- (near C155) 16MHz oscilator

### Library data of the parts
C144 C146 C154 C155 C158 C159 = CMP-0064924-2: as C35 on sheet RemoteIO_CPU_PWR_RST
C145 C147 C156 = CMP-0119242-1: as C167 on sheet RemoteIO_CPU_PWR_RST
C149-C153 C157 C162 = CMP-0119143-1: as C37 on sheet RemoteIO_CPU_PWR_RST
C160 C161 = CMP-0124909-1: 12 pF ±2% 50V Ceramic Capacitor C0G, NP0 0402 (1005 Metric); Manufacturer: Wurth; AEC Qualified: No; SizeZ_mm: 0.55mm; TempCo: 30ppm/°C; Value: 12pF
D28 = CMP-0122246-1: Red 624nm LED Indication - Discrete 2V 0402 (1005 Metric); Manufacturer: Wurth; Angle: 120°; LambdaP: 632nm; Power_TotalModule: 48mW; SizeZ_mm: 0.35mm; Tjmax_C: 115°C; Vr_V: 5V; AEC Qualified: No; Forward Current: 20mA; Led Orientation: Top View; Luminous Intensity: 110mcd
D29-D31 = CMP-0081765-2: LED, Green, SMD; Manufacturer: Wurth Elektronik; Vr_V: 5V; Io_A: 20mA; Tjmax_C: 95°C; Ir_A: 10µA; Power_TotalModule: 99mW; Value2: 3.2V; SizeArea_mm2: 0.5; SizeX_mm: 1; Value1: 0.099W; Angle: 120; Type: InGaN; SizeAreaWB_mm2: 3
D35 = CMP-0091708-1: 12.4V (Typ) Clamp 5.5A (8/20µs) Ipp Tvs Diode Surface Mount SC-70-3; Manufacturer: Texas Instruments; Standoff Height: 0mm; Clamping Voltage: 9.7V; AEC Qualified: No; Number Of Channels: 2; ValueDisplayed: 1.5pF; VRWM: 5.5V; Direction: Unidirectional; SizeZ_mm: 1.1mm; TaMin_C: -40°C; TaMax_C: +125°C; Breakdown Voltage: 6.5V; Ppk: 75W
J6 = CMP-0054798-2: Header, 2.54 mm, 4x1, Gold, TH; Manufacturer: Wurth Elektronik; PartNumber: 61300411121; Pitch_mm: 2.54; Gender: Male; Row_Count: 1; Cert_UL: Y; Shrouded: N
J7 = CMP-0086695-3: USB - micro B USB 2.0 Receptacle Connector 5 Position Surface Mount, Right Angle; Through Hole; Manufacturer: Wurth Electronics; Shrouded: true; Voltage_V: 30V; Current_A: 3A; ContactFinish: Gold
R194 = CMP-0026441-2: RES, 52.3 k, 1%, 0.063 W, AEC-Q200 Grade 0, 0402; Manufacturer: Vishay-Dale; Power_W: 63mW; TempCo: 100 ppm/C; Value_Code: 52k3; Value: 52.3k; EIA_Code: E96; SizeX_mm: 1; SizeY_mm: 0.5; SizeZ_mm: 0.6; Value2: 0.063W; AEC Qualified: Y; VDC_V: 50V; AEC Category: Q200; AEC Grade: 0
R195 R207 = CMP-0026918-5: RES, 3.3 k, 5%, 0.063 W, AEC-Q200 Grade 0, 0402; Manufacturer: Vishay-Dale; Power_W: 63mW; TempCo: 200 ppm/C; Value_Code: 3k30; Value: 3.3k; EIA_Code: E24; SizeX_mm: 1; SizeY_mm: 0.5; SizeZ_mm: 0.6; Value2: 0.063W; AEC Qualified: Y; VDC_V: 50V; AEC Category: Q200; AEC Grade: 0
R196 = CMP-0078244-2: RES, 30.0 k, 1%, 0.063 W, AEC-Q200 Grade 0, 0402; Manufacturer: Vishay-Dale; Power_W: 63mW; Green_Lifecycle: Active; TempCo: 100 ppm/C; Value_Code: 30k0; Green_REACh: Passed; Value: 30.0k; Res_ohm: 30k; SizeX_mm: 1; SizeY_mm: 0.5; SizeZ_mm: 0.6; Value2: 0.063W; AEC Qualified: Y; VDC_V: 50V; AEC Grade: 0; AEC Category: Q200
R197-R200 R206 = CMP-0026071-3: RES, 1.00 k, 1%, 0.063 W, AEC-Q200 Grade 0, 0402; Manufacturer: Vishay-Dale; Power_W: 63mW; TempCo: 100 ppm/C; Value_Code: 1k00; Value: 1.00k; EIA_Code: E96; Res_ohm: 1k; SizeX_mm: 1; SizeY_mm: 0.5; SizeZ_mm: 0.6; Value2: 0.063W; AEC Qualified: Y; VDC_V: 50V; AEC Category: Q200; AEC Grade: 0
R201 = CMP-0026824-3: RES, 100, 5%, 0.063 W, AEC-Q200 Grade 0, 0402; Manufacturer: Vishay-Dale; Value: 100; Value_Code: 100R; Power_W: 63mW; Value2: 0.063W; VDC_V: 50V; TempCo: 200 ppm/C; SizeArea_mm2: 0.5; SizeX_mm: 1; SizeZ_mm: 0.6; EIA_Code: E24; AEC Category: Q200; AEC Qualified: Y; AEC Grade: 0
R203-R205 R212 = CMP-0026880-3: as R151 on sheet RemoteIO_CPU_MISC
R208 R209 = CMP-0026825-5: as R100 on sheet RemoteIO_CPU_PWR_RST
R210 = CMP-0026413-2: RES, 4.87 k, 1%, 0.063 W, AEC-Q200 Grade 0, 0402; Manufacturer: Vishay-Dale; Value: 4.87k; Value_Code: 4k87; Power_W: 63mW; Value2: 0.063W; VDC_V: 50V; TempCo: 100 ppm/C; SizeArea_mm2: 0.5; SizeX_mm: 1; SizeZ_mm: 0.6; EIA_Code: E96; AEC Category: Q200; AEC Qualified: Y; AEC Grade: 0
R211 = CMP-0026946-3: RES, 51, 5%, 0.063 W, AEC-Q200 Grade 0, 0402; Manufacturer: Vishay-Dale; Value: 51; Value_Code: 51R0; Power_W: 63mW; Value2: 0.063W; VDC_V: 50V; TempCo: 200 ppm/C; SizeArea_mm2: 0.5; SizeX_mm: 1; SizeZ_mm: 0.6; EIA_Code: E24; AEC Category: Q200; AEC Qualified: Y; AEC Grade: 0
R213 = CMP-0025862-4: RES, 8.2 k, 5%, 0.1 W, AEC-Q200 Grade 0, 0603; Manufacturer: Vishay-Dale; Power_W: 100mW; TempCo: 200 ppm/C; Value_Code: 8k20; Value: 8.2k; EIA_Code: E24; SizeX_mm: 1.6; SizeY_mm: 0.8; SizeZ_mm: 1; Value2: 0.1W; SizeArea_mm2: 1.28; AEC Qualified: Y; VDC_V: 75V; AEC Category: Q200; AEC Grade: 0
TP9 = CMP-0078143-4: TEST POINT.  No entry in BOM.
U29 = CMP-0066914-5: 1% High-Accuracy, 1-A, Low-Dropout Regulator with Reverse Current Protection, DRV0006A (WSON-6); Manufacturer: Texas Instruments; Alternate PartNumber: TPS7A3701DRVT; SizeX_mm: 2; CompType: IC; SizeZ_mm: 0.8; SizeArea_mm2: 4; SizeAreaWB_mm2: 9; U/M: EA
U30 = CMP-0077953-1: MSP432E401YTPDT, PDT0128A (TQFP-128); Alternate PartNumber: MSP432E401YTPDTR; Alternate Manufacturer: Texas Instruments; SizeAreaWB_mm2: 324; SizeZ_mm: 1.2; SizeX_mm: 16; SizeArea_mm2: 256; CompType: IC; AEC Qualified: N; AEC Category: Q200
Y1 = CMP-0094478-1: Crystal 16 MHz ±20ppm Crystal 8pF 70 Ohms 4-SMD, No Lead; Manufacturer: Wurth; SizeZ_mm: 0.8mm; Frequency_Fixed: 16MHz; Esr: 70

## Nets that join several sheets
1V25: Power (R125.2 R141.2), RemoteIO_CPU_PWR_RST (C80.2 R109.2 U12.V7)
3V3: RemoteIO (TP12.1), Power (6 pins), Eth1 (12 pins), Eth2 (12 pins), RemoteIO_CPU_IO (5 pins), RemoteIO_IO (50 pins), RemoteIO_HSS (7 pins), RemoteIO_Flash (20 pins), RemoteIO_RAM (20 pins), RemoteIO_SOP (8 pins), RemoteIO_CPU_PWR_RST (10 pins), RemoteIO_CPU_MISC (5 pins)
24V: Power (8 pins), IOs/IO1 (C40.1.2 U1.1.9), IOs/IO2 (C40.2.2 U1.2.9), IOs/IO3 (C40.3.2 U1.3.9), IOs/IO4 (C40.4.2 U1.4.9), IOs/IO5 (C40.5.2 U1.5.9), IOs/IO6 (C40.6.2 U1.6.9), IOs/IO7 (C40.7.2 U1.7.9), IOs/IO8 (C40.8.2 U1.8.9), RemoteIO_HSS (20 pins)
EARTH: Eth1 (C140.1.2 J4.1.Shell R193.1.1), Eth2 (C140.2.2 J4.2.Shell R193.2.1), RemoteIO_Hardware (H2.1)
GND: RemoteIO (J8.1 J9.1), Power (26 pins), Eth1 (33 pins), Eth2 (33 pins), RemoteIO_CPU_IO (10 pins), RemoteIO_IO (18 pins), IOs/IO1 (18 pins), IOs/IO2 (18 pins), IOs/IO3 (18 pins), IOs/IO4 (18 pins), IOs/IO5 (18 pins), IOs/IO6 (18 pins), IOs/IO7 (18 pins), IOs/IO8 (18 pins), RemoteIO_Hardware (TP3.1 TP4.1 TP5.1), RemoteIO_HSS (30 pins), RemoteIO_Flash (10 pins), RemoteIO_RAM (10 pins), RemoteIO_SOP (9 pins), RemoteIO_CPU_PWR_RST (162 pins), RemoteIO_CPU_MISC (34 pins), RemoteIO_XDS110 (44 pins)
25MHz: Eth1 (C127.1.1 U19.1.9), RemoteIO_CPU_PWR_RST (R119.2)
25MHz: Eth2 (C127.2.1 U19.2.9), RemoteIO_CPU_PWR_RST (R118.2)
~{Fault}: RemoteIO_CPU_IO (U12.G1), IOs/IO1 (U1.1.20), IOs/IO2 (U1.2.20), IOs/IO3 (U1.3.20), IOs/IO4 (U1.4.20), IOs/IO5 (U1.5.20), IOs/IO6 (U1.6.20), IOs/IO7 (U1.7.20), IOs/IO8 (U1.8.20)
~{FLT}: RemoteIO_CPU_IO (U12.G2), RemoteIO_HSS (R29.1 U10.2 U11.2)
~{POR}: RemoteIO_SOP (R93.1), RemoteIO_CPU_PWR_RST (U12.V3 U20.4)
~{WARMRST}: Eth1 (C169.1.2 U26.1.1), Eth2 (C169.2.2 U26.2.1), RemoteIO_Flash (U18.2), RemoteIO_RAM (U17.2), RemoteIO_CPU_PWR_RST (C167.2 R113.2 U12.G3)
CS1: RemoteIO_CPU_IO (U12.F1), IOs/IO1 (U1.1.1)
CS2: RemoteIO_CPU_IO (U12.F2), IOs/IO2 (U1.2.1)
CS3: RemoteIO_CPU_IO (U12.E2), IOs/IO3 (U1.3.1)
CS4: RemoteIO_CPU_IO (U12.D1), IOs/IO4 (U1.4.1)
CS5: RemoteIO_CPU_IO (U12.D2), IOs/IO5 (U1.5.1)
CS6: RemoteIO_CPU_IO (U12.C2), IOs/IO6 (U1.6.1)
CS7: RemoteIO_CPU_IO (U12.C1), IOs/IO7 (U1.7.1)
CS8: RemoteIO_CPU_IO (U12.B2), IOs/IO8 (U1.8.1)
DCDC_PG: Power (R127.1 U24.6), RemoteIO_CPU_PWR_RST (U20.1)
DIN: RemoteIO_CPU_IO (R39.2), RemoteIO_IO (U3.14), IOs/IO1 (U1.1.24), IOs/IO2 (U1.2.24), IOs/IO3 (U1.3.24), IOs/IO4 (U1.4.24), IOs/IO5 (U1.5.24), IOs/IO6 (U1.6.24), IOs/IO7 (U1.7.24), IOs/IO8 (U1.8.24), RemoteIO_HSS (U10.8 U11.8)
DIO_EN1: RemoteIO_IO (U3.15), IOs/IO1 (U1.1.19)
DIO_EN2: RemoteIO_IO (U3.1), IOs/IO2 (U1.2.19)
DIO_EN3: RemoteIO_IO (U3.2), IOs/IO3 (U1.3.19)
DIO_EN4: RemoteIO_IO (U3.3), IOs/IO4 (U1.4.19)
DIO_EN5: RemoteIO_IO (U3.4), IOs/IO5 (U1.5.19)
DIO_EN6: RemoteIO_IO (U3.5), IOs/IO6 (U1.6.19)
DIO_EN7: RemoteIO_IO (U3.6), IOs/IO7 (U1.7.19)
DIO_EN8: RemoteIO_IO (U3.7), IOs/IO8 (U1.8.19)
DIO_RX1: RemoteIO_IO (U5.11), IOs/IO1 (U1.1.15)
DIO_RX2: RemoteIO_IO (U5.12), IOs/IO2 (U1.2.15)
DIO_RX3: RemoteIO_IO (U5.13), IOs/IO3 (U1.3.15)
DIO_RX4: RemoteIO_IO (U5.14), IOs/IO4 (U1.4.15)
DIO_RX5: RemoteIO_IO (U5.3), IOs/IO5 (U1.5.15)
DIO_RX6: RemoteIO_IO (U5.4), IOs/IO6 (U1.6.15)
DIO_RX7: RemoteIO_IO (U5.5), IOs/IO7 (U1.7.15)
DIO_RX8: RemoteIO_IO (U5.6), IOs/IO8 (U1.8.15)
DIO_TX1: RemoteIO_IO (U6.15), IOs/IO1 (U1.1.17)
DIO_TX2: RemoteIO_IO (U6.1), IOs/IO2 (U1.2.17)
DIO_TX3: RemoteIO_IO (U6.2), IOs/IO3 (U1.3.17)
DIO_TX4: RemoteIO_IO (U6.3), IOs/IO4 (U1.4.17)
DIO_TX5: RemoteIO_IO (U6.4), IOs/IO5 (U1.5.17)
DIO_TX6: RemoteIO_IO (U6.5), IOs/IO6 (U1.6.17)
DIO_TX7: RemoteIO_IO (U6.6), IOs/IO7 (U1.7.17)
DIO_TX8: RemoteIO_IO (U6.7), IOs/IO8 (U1.8.17)
DOUT: RemoteIO_CPU_IO (R35.1), RemoteIO_IO (U2.4), IOs/IO1 (U1.1.21), IOs/IO2 (U1.2.21), IOs/IO3 (U1.3.21), IOs/IO4 (U1.4.21), IOs/IO5 (U1.5.21), IOs/IO6 (U1.6.21), IOs/IO7 (U1.7.21), IOs/IO8 (U1.8.21), RemoteIO_HSS (U10.7 U11.7)
HSS_~{CS}: RemoteIO_CPU_IO (U12.B1), RemoteIO_HSS (U10.10 U11.10)
IO_EN1: RemoteIO_CPU_IO (U12.A18), IOs/IO1 (U1.1.3)
IO_EN2: RemoteIO_CPU_IO (U12.A13), IOs/IO2 (U1.2.3), RemoteIO_SOP (U15.8)
IO_EN3: RemoteIO_CPU_IO (U12.U1), IOs/IO3 (U1.3.3)
IO_EN4: RemoteIO_CPU_IO (U12.A19), IOs/IO4 (U1.4.3)
IO_EN5: RemoteIO_CPU_IO (U12.A16), IOs/IO5 (U1.5.3)
IO_EN6: RemoteIO_CPU_IO (U12.C3), IOs/IO6 (U1.6.3)
IO_EN7: RemoteIO_CPU_IO (U12.D8), IOs/IO7 (U1.7.3)
IO_EN8: RemoteIO_CPU_IO (U12.A3), IOs/IO8 (U1.8.3)
IO_RX1: RemoteIO_CPU_IO (U12.W16), IOs/IO1 (U1.1.2)
IO_RX2: RemoteIO_CPU_IO (U12.C16), IOs/IO2 (U1.2.2)
IO_RX3: RemoteIO_CPU_IO (U12.H2), IOs/IO3 (U1.3.2)
IO_RX4: RemoteIO_CPU_IO (U12.Y16), IOs/IO4 (U1.4.2)
IO_RX5: RemoteIO_CPU_IO (U12.B17), IOs/IO5 (U1.5.2)
IO_RX6: RemoteIO_CPU_IO (U12.E1), IOs/IO6 (U1.6.2)
IO_RX7: RemoteIO_CPU_IO (U12.A11), IOs/IO7 (U1.7.2)
IO_RX8: RemoteIO_CPU_IO (U12.C7), IOs/IO8 (U1.8.2)
IO_TX1: RemoteIO_CPU_IO (U12.A12), IOs/IO1 (U1.1.4)
IO_TX2: RemoteIO_CPU_IO (U12.D11), IOs/IO2 (U1.2.4)
IO_TX3: RemoteIO_CPU_IO (U12.D15), IOs/IO3 (U1.3.4)
IO_TX4: RemoteIO_CPU_IO (U12.C9), IOs/IO4 (U1.4.4)
IO_TX5: RemoteIO_CPU_IO (U12.Y17), IOs/IO5 (U1.5.4)
IO_TX6: RemoteIO_CPU_IO (U12.W17), IOs/IO6 (U1.6.4)
IO_TX7: RemoteIO_CPU_IO (U12.R1), IOs/IO7 (U1.7.4), RemoteIO_SOP (U15.6)
IO_TX8: RemoteIO_CPU_IO (U12.R2), IOs/IO8 (U1.8.4), RemoteIO_SOP (U15.3)
JTAG_TCK: RemoteIO_CPU_MISC (J3.11 R147.1 R151.1), RemoteIO_XDS110 (R203.1)
JTAG_TDI: RemoteIO_CPU_MISC (J3.3 R148.1 R152.1), RemoteIO_XDS110 (R212.1)
JTAG_TDO: RemoteIO_CPU_MISC (J3.7 R149.1 R153.1), RemoteIO_XDS110 (R205.1)
JTAG_TMS: RemoteIO_CPU_MISC (J3.1 R150.1 R154.1), RemoteIO_XDS110 (R204.1)
L+1: IOs/IO1 (9 pins), RemoteIO_HSS (7 pins)
L+2: IOs/IO2 (9 pins), RemoteIO_HSS (7 pins)
L+3: IOs/IO3 (9 pins), RemoteIO_HSS (7 pins)
L+4: IOs/IO4 (9 pins), RemoteIO_HSS (7 pins)
L+5: IOs/IO5 (9 pins), RemoteIO_HSS (7 pins)
L+6: IOs/IO6 (9 pins), RemoteIO_HSS (7 pins)
L+7: IOs/IO7 (9 pins), RemoteIO_HSS (7 pins)
L+8: IOs/IO8 (9 pins), RemoteIO_HSS (7 pins)
LED_ERR: RemoteIO_CPU_IO (D23.2 U12.B12), RemoteIO_SOP (U15.11)
LED_Link: Eth1 (5 pins), RemoteIO_CPU_IO (U12.J18)
LED_Link: Eth2 (5 pins), RemoteIO_CPU_IO (U12.G18)
MII1_RX_ER: Eth1 (R171.1.1 R181.1.2 U19.1.20), RemoteIO_CPU_IO (U12.K19)
MII1_RXCLK: Eth1 (U19.1.19), RemoteIO_CPU_IO (U12.N20)
MII1_RXD0: Eth1 (U19.1.16), RemoteIO_CPU_IO (U12.N17)
MII1_RXD1: Eth1 (U19.1.15), RemoteIO_CPU_IO (U12.N19)
MII1_RXD2: Eth1 (U19.1.14), RemoteIO_CPU_IO (U12.M18)
MII1_RXD3: Eth1 (R172.1.1 R182.1.2 U19.1.13), RemoteIO_CPU_IO (U12.M20)
MII1_RXDV: Eth1 (U19.1.18), RemoteIO_CPU_IO (U12.L20)
MII1_TXCLK: Eth1 (U19.1.22), RemoteIO_CPU_IO (U12.M19)
MII1_TXD0: Eth1 (U19.1.24), RemoteIO_CPU_IO (U12.P20)
MII1_TXD1: Eth1 (U19.1.25), RemoteIO_CPU_IO (U12.P19)
MII1_TXD2: Eth1 (U19.1.26), RemoteIO_CPU_IO (U12.K20)
MII1_TXD3: Eth1 (U19.1.27), RemoteIO_CPU_IO (U12.L19)
MII1_TXEN: Eth1 (U19.1.23), RemoteIO_CPU_IO (U12.P18)
MII2_RX_ER: Eth2 (R171.2.1 R181.2.2 U19.2.20), RemoteIO_CPU_IO (U12.F20)
MII2_RXCLK: Eth2 (U19.2.19), RemoteIO_CPU_IO (U12.F19)
MII2_RXD0: Eth2 (U19.2.16), RemoteIO_CPU_IO (U12.H20)
MII2_RXD1: Eth2 (U19.2.15), RemoteIO_CPU_IO (U12.H19)
MII2_RXD2: Eth2 (U19.2.14), RemoteIO_CPU_IO (U12.H17)
MII2_RXD3: Eth2 (R172.2.1 R182.2.2 U19.2.13), RemoteIO_CPU_IO (U12.G20)
MII2_RXDV: Eth2 (U19.2.18), RemoteIO_CPU_IO (U12.G19)
MII2_TXCLK: Eth2 (U19.2.22), RemoteIO_CPU_IO (U12.B20)
MII2_TXD0: Eth2 (U19.2.24), RemoteIO_CPU_IO (U12.F17)
MII2_TXD1: Eth2 (U19.2.25), RemoteIO_CPU_IO (U12.D20)
MII2_TXD2: Eth2 (U19.2.26), RemoteIO_CPU_IO (U12.C20)
MII2_TXD3: Eth2 (U19.2.27), RemoteIO_CPU_IO (U12.D19)
MII2_TXEN: Eth2 (U19.2.23), RemoteIO_CPU_IO (U12.E18)
NetJ9_2: RemoteIO (J9.2), RemoteIO_CPU_IO (U12.K2)
NetJ9_3: RemoteIO (J9.3), RemoteIO_CPU_IO (U12.A10)
NetR41_2: Eth1 (U19.1.11), Eth2 (U19.2.11), RemoteIO_CPU_IO (R41.2 R115.1 U12.R19)
NetR114_1: Eth1 (U19.1.12), Eth2 (U19.2.12), RemoteIO_CPU_IO (R114.1 U12.R20)
OSPI0_~{CS}: RemoteIO_CPU_IO (U12.L2), RemoteIO_Flash (R43.1 U13.C2)
OSPI0_CLK: RemoteIO_CPU_IO (R85.1), RemoteIO_Flash (R62.2 U13.B2)
OSPI0_D0: RemoteIO_CPU_IO (U12.M3), RemoteIO_Flash (R44.1 R53.1)
OSPI0_D1: RemoteIO_CPU_IO (U12.M2), RemoteIO_Flash (R45.1 R54.1)
OSPI0_D2: RemoteIO_CPU_IO (U12.P1), RemoteIO_Flash (R46.1 R55.1)
OSPI0_D3: RemoteIO_CPU_IO (U12.L1), RemoteIO_Flash (R47.1 R56.1)
OSPI0_D4: RemoteIO_CPU_IO (U12.R4), RemoteIO_Flash (R48.1 R57.1)
OSPI0_D5: RemoteIO_CPU_IO (U12.K1), RemoteIO_Flash (R49.1 R58.1)
OSPI0_D6: RemoteIO_CPU_IO (U12.P2), RemoteIO_Flash (R50.1 R59.1)
OSPI0_D7: RemoteIO_CPU_IO (U12.L4), RemoteIO_Flash (R51.1 R60.1)
OSPI0_DQS: RemoteIO_CPU_IO (U12.N2), RemoteIO_Flash (R52.1 R61.2)
OSPI0_ECC_FAIL: RemoteIO_CPU_IO (U12.J3), RemoteIO_Flash (R42.1 U13.A5)
OSPI0_RST: RemoteIO_CPU_IO (R98.1), RemoteIO_Flash (R97.1 U18.1)
OSPI1_~{CS}: RemoteIO_CPU_IO (U12.V20), RemoteIO_RAM (R64.1 R87.1 R88.1)
OSPI1_CLK: RemoteIO_CPU_IO (R86.1), RemoteIO_RAM (R84.2 U14.B2)
OSPI1_D0: RemoteIO_CPU_IO (U12.V19), RemoteIO_RAM (R65.1 R75.1)
OSPI1_D1: RemoteIO_CPU_IO (U12.Y18), RemoteIO_RAM (R66.1 R76.1)
OSPI1_D2: RemoteIO_CPU_IO (U12.W18), RemoteIO_RAM (R67.1 R77.1)
OSPI1_D3: RemoteIO_CPU_IO (U12.Y19), RemoteIO_RAM (R68.1 R78.1)
OSPI1_D4: RemoteIO_CPU_IO (U12.W19), RemoteIO_RAM (R69.1 R79.1)
OSPI1_D5: RemoteIO_CPU_IO (U12.U20), RemoteIO_RAM (R70.1 R80.1)
OSPI1_D6: RemoteIO_CPU_IO (U12.T20), RemoteIO_RAM (R71.1 R81.1)
OSPI1_D7: RemoteIO_CPU_IO (U12.V18), RemoteIO_RAM (R72.1 R82.1)
OSPI1_DQS: RemoteIO_CPU_IO (U12.U19), RemoteIO_RAM (R74.1 R83.2)
OSPI1_ECC_FAIL: RemoteIO_CPU_IO (U12.T19), RemoteIO_RAM (R63.1 R73.1)
OSPI1_RST: RemoteIO_CPU_IO (R99.1), RemoteIO_RAM (R95.1 U17.1)
RESET_PHY0: Eth1 (U26.1.2), RemoteIO_CPU_IO (U12.U4)
RESET_PHY1: Eth2 (U26.2.2), RemoteIO_CPU_IO (U12.C12)
SCLK: RemoteIO_CPU_IO (R40.2), RemoteIO_IO (6 pins), IOs/IO1 (U1.1.22), IOs/IO2 (U1.2.22), IOs/IO3 (U1.3.22), IOs/IO4 (U1.4.22), IOs/IO5 (U1.5.22), IOs/IO6 (U1.6.22), IOs/IO7 (U1.7.22), IOs/IO8 (U1.8.22), RemoteIO_HSS (U10.9 U11.9)
SR_~{CS}: RemoteIO_CPU_IO (U12.M1), RemoteIO_IO (7 pins)
UART0_RX: RemoteIO_CPU_IO (U12.A8), RemoteIO_XDS110 (U30.34)
UART0_TX: RemoteIO_CPU_IO (U12.B8), RemoteIO_XDS110 (U30.33)
UART1_RX: RemoteIO (J8.2), RemoteIO_CPU_IO (U12.T3)
UART1_TX: RemoteIO (J8.3), RemoteIO_CPU_IO (U12.K4)

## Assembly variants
001: not fitted C119 C127.1 C127.2 FID1 FID2 FID3 R73 R87 R98 R102 R103 R104 R105 R106 R131 R155 R156 R157 R158 R159 R160 R161 R162 R166.1 R166.2 R168.1 R177.1 R177.2 R178.1 R178.2 R181.1 R181.2 R182.1 R182.2 R190.1 R190.2 R209 RV1.1 RV1.2 RV1.3 RV1.4 RV1.5 RV1.6 RV1.7 RV1.8 RV2.1 RV2.2 RV2.3 RV2.4 RV2.5 RV2.6 RV2.7 RV2.8 RV3.1 RV3.2 RV3.3 RV3.4 RV3.5 RV3.6 RV3.7 RV3.8 RV4.1 RV4.2 RV4.3 RV4.4 RV4.5 RV4.6 RV4.7 RV4.8 RV5.1 RV5.2 RV5.3 RV5.4 RV5.5 RV5.6 RV5.7 RV5.8 RV6.1 RV6.2 RV6.3 RV6.4 RV6.5 RV6.6 RV6.7 RV6.8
